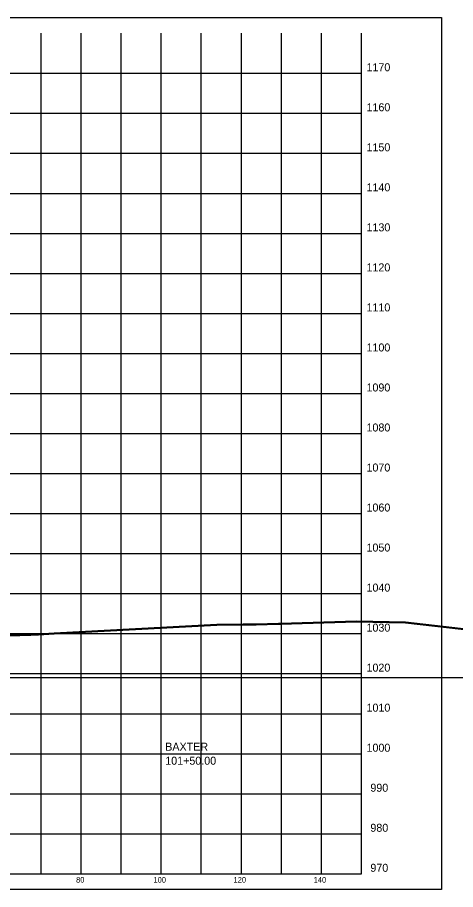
# Model space of a CAD drawing. Extents: x 5868 to 6683, y 2883 to 19120.
# Drawn here: x 6257.9 to 6367.3, y 4392.1 to 4610 of the extents above; entities that cross this region are included whole.
import ezdxf

# ---------------------------------------------------------------- set-up
doc = ezdxf.new("R2010")
doc.units = 0
for name, color, linetype in [('DESIGN - SHEET - Corner Text', 7, 'Continuous'), ('DESIGN - SHEET - Light Grid', 7, 'Continuous'), ('DESIGN - SHEET - Linework', 7, 'Continuous'), ('DESIGN - SHEET - Plot Shape', 7, 'Continuous'), ('DESIGN - TYPICAL - Warning Text', 7, 'Continuous'), ('SURVEY - GROUND - Bottom of Topsoil Layer', 7, 'Continuous'), ('SURVEY - GROUND - Top of Ground', 7, 'Continuous')]:
    doc.layers.add(name, color=color, linetype=linetype)

msp = doc.modelspace()

# ---------------------------------------------------------------- linework, layer by layer
at = {"layer": 'DESIGN - SHEET - Light Grid'}
msp.add_line((6193.78, 4445.07), (6493.78, 4445.07), dxfattribs=at)
at = {"layer": 'DESIGN - SHEET - Linework'}
for p, q in [((6263.78, 4396.07), (6263.78, 4606.07)), ((6273.78, 4396.07), (6273.78, 4606.07)), ((6283.78, 4396.07), (6283.78, 4606.07)), ((6293.78, 4396.07), (6293.78, 4606.07)), ((6303.78, 4396.07), (6303.78, 4606.07)), ((6313.78, 4396.07), (6313.78, 4606.07)), ((6323.78, 4396.07), (6323.78, 4606.07)), ((6333.78, 4396.07), (6333.78, 4606.07)), ((6043.78, 4596.07), (6343.78, 4596.07)), ((6043.78, 4586.07), (6343.78, 4586.07)), ((6043.78, 4576.07), (6343.78, 4576.07)), ((6043.78, 4566.07), (6343.78, 4566.07)), ((6043.78, 4556.07), (6343.78, 4556.07)), ((6043.78, 4546.07), (6343.78, 4546.07)), ((6043.78, 4536.07), (6343.78, 4536.07)), ((6043.78, 4526.07), (6343.78, 4526.07)), ((6043.78, 4516.07), (6343.78, 4516.07)), ((6043.78, 4506.07), (6343.78, 4506.07)), ((6043.78, 4496.07), (6343.78, 4496.07)), ((6043.78, 4486.07), (6343.78, 4486.07)), ((6043.78, 4476.07), (6343.78, 4476.07)), ((6043.78, 4466.07), (6343.78, 4466.07)), ((6043.78, 4456.07), (6343.78, 4456.07)), ((6043.78, 4446.07), (6343.78, 4446.07)), ((6043.78, 4436.07), (6343.78, 4436.07)), ((6043.78, 4426.07), (6343.78, 4426.07)), ((6043.78, 4416.07), (6343.78, 4416.07)), ((6043.78, 4406.07), (6343.78, 4406.07))]:
    msp.add_line(p, q, dxfattribs=at)
msp.add_lwpolyline([(6043.78, 4606.07), (6043.78, 4396.07), (6343.78, 4396.07), (6343.78, 4606.07)], dxfattribs=at)
at = {"layer": 'DESIGN - SHEET - Plot Shape'}
msp.add_lwpolyline([(6023.78, 4610.01), (6363.78, 4610.01), (6363.78, 4392.13), (6023.78, 4392.13)], close=True, dxfattribs=at)
at = {"layer": 'SURVEY - GROUND - Bottom of Topsoil Layer'}
for p, q in [((6267.06, 4455.98), (6307.67, 4458.2)), ((6307.67, 4458.2), (6314.23, 4458.27)), ((6314.23, 4458.27), (6317.52, 4458.29)), ((6317.52, 4458.29), (6323.07, 4458.41)), ((6323.07, 4458.41), (6323.58, 4458.43)), ((6323.58, 4458.43), (6342.53, 4459.05)), ((6342.53, 4459.05), (6354.76, 4458.79)), ((6354.76, 4458.79), (6408.27, 4452.62)), ((6226.89, 4454.6), (6261.19, 4455.66)), ((6261.19, 4455.66), (6263.13, 4455.79)), ((6263.13, 4455.79), (6267.06, 4455.98))]:
    msp.add_line(p, q, dxfattribs=at)
at = {"layer": 'SURVEY - GROUND - Top of Ground'}
msp.add_lwpolyline([(6226.89, 4454.85), (6261.19, 4455.91), (6263.13, 4456.04), (6267.06, 4456.23), (6307.67, 4458.45), (6314.23, 4458.52), (6317.52, 4458.54), (6323.07, 4458.66), (6323.58, 4458.68), (6342.53, 4459.3), (6354.76, 4459.04), (6408.27, 4452.87)], dxfattribs=at)

# ---------------------------------------------------------------- texts
at = {"layer": 'DESIGN - SHEET - Corner Text'}
for s, height, p in [('1170', 2, (6345.03, 4596.57)), ('1160', 2, (6345.03, 4586.57)), ('1150', 2, (6345.03, 4576.57)), ('1140', 2, (6345.03, 4566.57)), ('1130', 2, (6345.03, 4556.57)), ('1120', 2, (6345.03, 4546.57)), ('1110', 2, (6345.03, 4536.57)), ('1100', 2, (6345.03, 4526.57)), ('1090', 2, (6345.03, 4516.57)), ('1080', 2, (6345.03, 4506.57)), ('1070', 2, (6345.03, 4496.57)), ('1060', 2, (6345.03, 4486.57)), ('1050', 2, (6345.03, 4476.57)), ('1040', 2, (6345.03, 4466.57)), ('1030', 2, (6345.03, 4456.57)), ('1020', 2, (6345.03, 4446.57)), ('1010', 2, (6345.03, 4436.57)), ('1000', 2, (6345.03, 4426.57)), ('990', 2, (6346, 4416.57)), ('980', 2, (6346, 4406.57)), ('970', 2, (6346, 4396.57)), ('80', 1.4, (6272.52, 4393.87)), ('100', 1.4, (6291.84, 4393.87)), ('120', 1.4, (6311.84, 4393.87)), ('140', 1.4, (6331.84, 4393.87))]:
    msp.add_text(s, height=height, dxfattribs=at).set_placement(p)
at = {"layer": 'DESIGN - TYPICAL - Warning Text'}
for s, p in [('BAXTER', (6294.78, 4426.82)), ('101+50.00', (6294.78, 4423.32))]:
    msp.add_text(s, height=2, dxfattribs=at).set_placement(p)

doc.saveas('drawing.dxf')
